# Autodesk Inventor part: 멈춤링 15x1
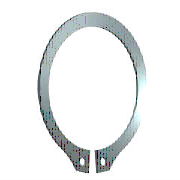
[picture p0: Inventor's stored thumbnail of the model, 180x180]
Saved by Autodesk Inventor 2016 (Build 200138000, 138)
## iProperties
Created: 2015-09
Part Number: 멈춤링 15x1
Material: 강철, 연강
Description: 리테이닝 링(C형)
Document SubType Name: Modeling
Standard: KS B 1336
Designer: mm
Standards Organization: KS
Language: ko-KR
Size Designation: 15 x 1
Categories: <MemberInstance><Categories><Category DisplayName="샤프트 부품" InternalName="7f7aeb1f-a693-4053-b835-cee3144e0d98" Mnemonic="SHFT"><Category DisplayName="써클립" Inter
Density: 1 g/cm^3
Appearance: 파란색 - 벽 페인트 - 광택
IsCustomPart: 1
Author: mduedu
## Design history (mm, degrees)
sketch "스케치1"
  geometry: L1 (-6, 0)-(6, 0) reference; L2 (0, 20.189)-(0, -80.536) reference; L3 (-48.09, 0)-(48.09, 0) reference; L4 (-0.425, -14.637)-(-0.425, -18.137); L5 (-0.425, -6.54)-(-0.425, -13.29); L6 (-2.795, 2.1)-(3.672, 2.1); L7 (0.425, -6.54)-(0.425, -13.29); L8 (0.425, -14.637)-(0.425, -18.137); C1 r 0.85 at (-1.7, -16.283); C2 r 0.85 at (1.7, -16.283); A1 r 7.15 centre (0, -7.5) between (0.425, -14.637) and (-0.425, -14.637); A2 r 9.075 centre (0, -6.975) between (4.291, -14.971) and (-4.291, -14.971); A3 r 10.646 centre (0, -7.5) between (-2.023, -17.952) and (-0.425, -18.137); A4 r 1.7 centre (-1.7, -16.283) between (-3.397, -16.376) and (-2.023, -17.952); A5 r 1.7 centre (-5.095, -16.469) between (-3.397, -16.376) and (-4.291, -14.971); A6 r 1.7 centre (5.095, -16.469) between (4.291, -14.971) and (3.397, -16.376); A7 r 1.7 centre (1.7, -16.283) between (2.023, -17.952) and (3.397, -16.376); A8 r 10.646 centre (0, -7.5) between (0.425, -18.137) and (2.023, -17.952)
  constraints: 16 point on circle, 12 end point, 10 centre point, 9 symmetric about line, 5 point on line, 4 tangent, 3 coincident, 2 horizontal, 1 perpendicular, 1 vertical, 5 other
  dimensions: "d0" = 14.3 diameter of A1 (= ND); "d1" = 3.5 distance of L4.end L4.start (= SRB2); "d6" = 0.425 distance between parallel lines of L2 L5 (= 0.25 x SD5); "d7" = 2.1 distance between parallel lines of L6 L3 (= SRB1); "d8" = 0.525 distance of A1.centre A2.centre (= 0.25 x SRB1); "d9" = 1.7 radius of A4 (= SD5); "d10" = 1.7 radius of A5 (= SD5); "d11" = 1.275 distance from line of L4 A4.centre (= 0.75 x SD5); "d12" = 1.7 diameter of C1 (= SD5); "d13" = 1.7 diameter of C2 (= SD5); "d14" = 7.5 distance from line of A1.centre L1 (= 0.5 x WD)
extrude "본체" new body sketch "스케치1" distance "d2" = 1 (= SD); taper "d3" = 0 deg
workaxis "Work Axis1"
workplane "Work Plane1"
body "Solid1"
other parameters: "WD" = 15 (= WDMIN) [user parameter; used in 1 equation term], "SD" = 1 [user parameter; used in 1 equation term], "SRB1" = 2.1 [user parameter; used in 2 equation terms], "ND" = 14.3 [user parameter; used in 1 equation term], "SRB2" = 3.5 [user parameter; used in 1 equation term], "SD5" = 1.7 [user parameter; used in 6 equation terms], "d15" = 0, "d16" = 0, "d17" = 0, "d41" = 0, "d42" = 0, "WDMIN" = 15 [user parameter; used in 1 equation term], "SD3" = 13.8 [user parameter], "WDMAX" = 16 [user parameter]
